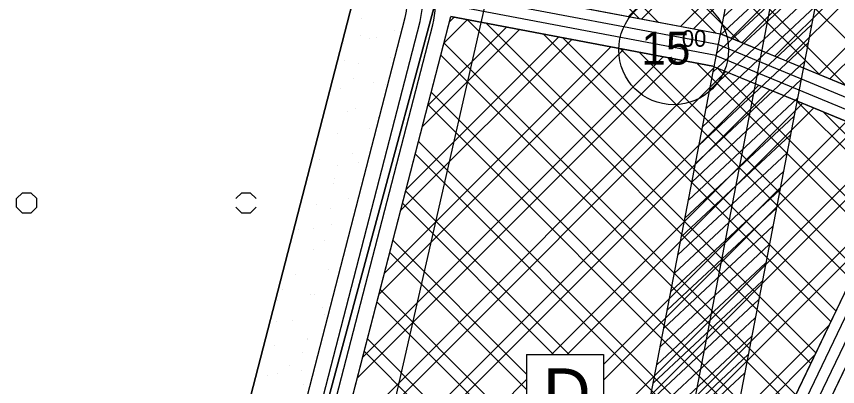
# Model space of a CAD drawing. Extents: x 419109 to 421295, y 4452223 to 4457798.
# Drawn here: x 419705 to 420079.2, y 4455807.8 to 4455976.5 of the extents above; entities that cross this region are included whole.
import ezdxf

# ---------------------------------------------------------------- set-up
doc = ezdxf.new("R2010")
doc.units = 0
for name, color, linetype in [('ADAKENARI', 7, 'Continuous'), ('KALDIRIM_FAT', 7, 'Continuous'), ('KD_DAIRE', 7, 'Continuous'), ('KD_YGEN', 7, 'Continuous'), ('PL_AYA_PARK_DINLENME', 7, 'Continuous'), ('PL_K_DEPOLAMA', 7, 'Continuous'), ('PL_KA_TARIM_ALANI', 7, 'Continuous'), ('PL_TİCARET', 7, 'Continuous'), ('PL_TOPLU_ISYERI', 7, 'Continuous'), ('SEMBOL_FAT', 7, 'Continuous'), ('TA_ENH_154', 7, 'Continuous'), ('TA_ENH_KORUMA', 7, 'Continuous'), ('TA_ENH_TARAMA', 7, 'Continuous'), ('TR_TARIMALANI', 7, 'Continuous'), ('TRFAT_DEPOLAMA', 7, 'Continuous'), ('TRFAT_PARKALANI', 7, 'Continuous'), ('TRFAT_TOPLUİŞYERLERİ', 7, 'Continuous')]:
    doc.layers.add(name, color=color, linetype=linetype)

msp = doc.modelspace()

# ---------------------------------------------------------------- linework, layer by layer
at = {"layer": 'ADAKENARI'}
for p, q in [((420026.68, 4455968.26), (419902.33, 4455991.81)), ((419802.57, 4455768.04), (419857.93, 4455982.18)), ((419826.78, 4455761.78), (419882.14, 4455975.93)), ((419846.14, 4455756.78), (419902.93, 4455976.43)), ((420022.37, 4455953.81), (419902.93, 4455976.43)), ((420026.68, 4455968.26), (420134.21, 4455923.79)), ((420022.37, 4455953.81), (420113.83, 4455915.99)), ((420043.17, 4455733.9), (420134.21, 4455923.79)), ((420029.83, 4455740.78), (420113.83, 4455915.99))]:
    msp.add_line(p, q, dxfattribs=at)
msp.add_arc((419853.67, 4455983.29), 29.41, 345.5054, 77.7533, dxfattribs=at)
at = {"layer": 'KALDIRIM_FAT'}
for p, q in [((420025.24, 4455963.44), (419895.82, 4455987.95)), ((420023.8, 4455958.63), (419896.07, 4455982.82)), ((419833.56, 4455760.03), (419888.92, 4455974.18)), ((419839.36, 4455758.53), (419894.72, 4455972.67)), ((420025.24, 4455963.44), (420120.05, 4455924.24)), ((420023.8, 4455958.63), (420118.13, 4455919.62)), ((420034.28, 4455738.49), (420119.46, 4455916.16)), ((420038.73, 4455736.19), (420123.97, 4455914))]:
    msp.add_line(p, q, dxfattribs=at)
for radius in [42.41, 36.41]:
    msp.add_arc((419853.67, 4455983.29), radius, 345.5054, 77.7533, dxfattribs=at)
at = {"layer": 'KD_DAIRE'}
msp.add_circle((420004.49, 4455961.2), 25, dxfattribs=at)
at = {"layer": 'PL_AYA_PARK_DINLENME'}
for p, q in [((419857.93, 4455982.18), (419802.57, 4455768.04)), ((419826.78, 4455761.78), (419882.14, 4455975.93))]:
    msp.add_line(p, q, dxfattribs=at)
for points in [[(420016.8, 4456927.25), (420013.63, 4456854.22), (420021.56, 4456763.74), (419972.35, 4456528.79), (419896.15, 4456444.66), (419851.71, 4456390.68), (419781.86, 4456219.24), (419743.76, 4456181.14), (419715.18, 4456046.21), (419900.92, 4456001.76), (419824.72, 4455719.19), (419823.13, 4455660.45), (419756.46, 4455592.19), (419783.44, 4455525.52), (419794.56, 4455425.51), (419778.68, 4455323.91)], [(419804.18, 4455325.18), (419819.77, 4455424.95), (419807.91, 4455531.7), (419785.76, 4455586.42), (419835.59, 4455637.43), (419842.19, 4455646.09), (419927.54, 4456021.09), (419744.69, 4456064.85), (419766.68, 4456168.71), (419803.1, 4456205.13), (419873.42, 4456377.73), (419915.08, 4456428.31), (419995.43, 4456517.04), (420046.79, 4456762.24), (420038.67, 4456854.78), (420041.73, 4456924.97)]]:
    msp.add_lwpolyline(points, dxfattribs=at)
msp.add_arc((419853.67, 4455983.29), 29.41, 345.5054, 77.7533, dxfattribs=at)
at = {"layer": 'PL_K_DEPOLAMA'}
msp.add_lwpolyline([(419846.14, 4455756.78), (419902.93, 4455976.43), (420022.37, 4455953.81), (420113.83, 4455915.99), (420029.83, 4455740.78)], dxfattribs=at)
at = {"layer": 'PL_KA_TARIM_ALANI'}
msp.add_lwpolyline([(419792.54, 4455014.98), (419819.96, 4455165.16), (419778.68, 4455323.91), (419794.56, 4455425.51), (419783.44, 4455525.52), (419756.46, 4455592.19), (419823.13, 4455660.45), (419824.72, 4455719.19), (419900.92, 4456001.76), (419869.84, 4456009.19), (419715.18, 4456046.21), (419743.76, 4456181.14), (419781.86, 4456219.24), (419851.71, 4456390.68), (419896.15, 4456444.66), (419972.35, 4456528.79), (420021.56, 4456763.74), (420013.63, 4456854.22), (420016.8, 4456927.25), (420027.91, 4457006.62), (420158.52, 4456994.43), (420142.12, 4457086.4)], dxfattribs=at)
at = {"layer": 'PL_TİCARET'}
msp.add_lwpolyline([(420153.07, 4455976.48), (420152.11, 4455974.16), (420151.45, 4455961.22), (420137.18, 4455930.24), (420134.21, 4455923.79), (420043.17, 4455733.9), (419945.46, 4455556.86), (419940.17, 4455559.7)], dxfattribs=at)
at = {"layer": 'PL_TOPLU_ISYERI'}
msp.add_lwpolyline([(420153.07, 4455976.48), (420152.11, 4455974.16), (420151.45, 4455961.22), (420137.18, 4455930.24), (420134.21, 4455923.79), (420026.68, 4455968.26), (419902.33, 4455991.81)], dxfattribs=at)
at = {"layer": 'SEMBOL_FAT'}
for p, q in [((419937.51, 4455822.43), (419937.51, 4455787.43)), ((419937.51, 4455822.43), (419972.51, 4455822.43)), ((419972.51, 4455822.43), (419972.51, 4455787.43))]:
    msp.add_line(p, q, dxfattribs=at)
at = {"layer": 'TA_ENH_154'}
msp.add_lwpolyline([(419862.83, 4455014.24), (420170.14, 4456613.6), (420230.68, 4456928.68), (420176.89, 4457440.84), (420133.44, 4457787.81)], dxfattribs=at)
at = {"layer": 'TA_ENH_KORUMA'}
msp.add_line((419842.5, 4455014.45), (420150.5, 4456617.38), dxfattribs=at)
msp.add_lwpolyline([(420153.62, 4457787.6), (420196.76, 4457443.12), (420250.88, 4456927.82), (420189.78, 4456609.83), (419883.15, 4455014.02)], dxfattribs=at)
at = {"layer": 'TA_ENH_TARAMA'}
for p, q in [((420027.3, 4455976.24), (420076.95, 4456022.64)), ((420025.7, 4455967.89), (420075.35, 4456014.3)), ((420024.09, 4455959.55), (420073.75, 4456005.95)), ((420022.49, 4455951.21), (420072.14, 4455997.61)), ((420020.89, 4455942.87), (420070.54, 4455989.27)), ((420019.29, 4455934.53), (420068.94, 4455980.93)), ((420017.68, 4455926.18), (420067.33, 4455972.58)), ((420016.08, 4455917.84), (420065.73, 4455964.24)), ((420014.48, 4455909.5), (420064.13, 4455955.9)), ((420012.87, 4455901.16), (420062.53, 4455947.56)), ((420011.27, 4455892.81), (420060.92, 4455939.22)), ((420009.67, 4455884.47), (420059.32, 4455930.87)), ((420008.07, 4455876.13), (420057.72, 4455922.53)), ((420006.46, 4455867.79), (420056.11, 4455914.19)), ((420004.86, 4455859.45), (420054.51, 4455905.85)), ((420003.26, 4455851.1), (420052.91, 4455897.5)), ((420001.65, 4455842.76), (420051.31, 4455889.16)), ((420000.05, 4455834.42), (420049.7, 4455880.82)), ((419998.45, 4455826.08), (420048.1, 4455872.48)), ((419996.84, 4455817.73), (420046.5, 4455864.14)), ((419995.24, 4455809.39), (420044.89, 4455855.79)), ((419993.64, 4455801.05), (420043.29, 4455847.45)), ((419992.04, 4455792.71), (420041.69, 4455839.11)), ((419990.43, 4455784.37), (420040.08, 4455830.77)), ((419988.83, 4455776.02), (420038.48, 4455822.42)), ((419987.23, 4455767.68), (420036.88, 4455814.08))]:
    msp.add_line(p, q, dxfattribs=at)
at = {"layer": 'TR_TARIMALANI'}
for p, q in [((419705, 4455893.42), (419707.71, 4455896.12)), ((419707.75, 4455896.14), (419711.58, 4455896.14)), ((419714.25, 4455893.42), (419711.54, 4455896.12)), ((419805, 4455893.42), (419807.71, 4455896.12)), ((419807.75, 4455896.14), (419811.58, 4455896.14)), ((419814.25, 4455893.42), (419811.54, 4455896.12)), ((419705.04, 4455889.6), (419705.04, 4455893.43)), ((419714.29, 4455889.6), (419714.29, 4455893.43)), ((419707.71, 4455886.88), (419705, 4455889.58)), ((419711.54, 4455886.88), (419714.25, 4455889.58)), ((419807.71, 4455886.88), (419805, 4455889.58)), ((419811.54, 4455886.88), (419814.25, 4455889.58)), ((419707.75, 4455886.89), (419711.58, 4455886.89)), ((419807.75, 4455886.89), (419811.58, 4455886.89))]:
    msp.add_line(p, q, dxfattribs=at)
at = {"layer": 'TRFAT_DEPOLAMA'}
for p, q in [((419899.78, 4455964.26), (419910.51, 4455974.99)), ((419902.25, 4455973.8), (419904.56, 4455976.12)), ((419910.36, 4455975.02), (420067.03, 4455818.35)), ((419889.92, 4455926.12), (419934.29, 4455970.49)), ((419892.38, 4455935.65), (419928.35, 4455971.61)), ((419919.08, 4455973.37), (420069.32, 4455823.13)), ((419882.52, 4455897.51), (419952.13, 4455967.11)), ((419945.25, 4455968.41), (420076.19, 4455837.47)), ((419953.97, 4455966.76), (420078.48, 4455842.25)), ((419872.66, 4455859.36), (419975.91, 4455962.61)), ((419880.06, 4455887.97), (419958.07, 4455965.99)), ((419899.81, 4455964.36), (420060.15, 4455804.01)), ((419870.2, 4455849.83), (419981.85, 4455961.48)), ((419898.35, 4455958.74), (420057.86, 4455799.23)), ((419980.14, 4455961.81), (420085.36, 4455856.59)), ((419988.86, 4455960.15), (420087.65, 4455861.37)), ((419860.34, 4455811.68), (420005.63, 4455956.98)), ((419862.8, 4455821.22), (419999.69, 4455958.1)), ((420015.03, 4455955.2), (420094.52, 4455875.71)), ((419850.47, 4455773.54), (420028.3, 4455951.36)), ((419852.94, 4455783.07), (420023.29, 4455953.43)), ((420024.28, 4455953.02), (420096.81, 4455880.49)), ((419844.49, 4455746.34), (420043.3, 4455945.15)), ((419844.5, 4455739.28), (420048.31, 4455943.08)), ((419894, 4455941.88), (420050.99, 4455784.89)), ((419892.54, 4455936.27), (420048.69, 4455780.11)), ((419948.87, 4455822.43), (420063.31, 4455936.88)), ((420060.45, 4455938.06), (420103.69, 4455894.83)), ((419955.94, 4455822.43), (420068.32, 4455934.81)), ((420072.51, 4455933.08), (420105.98, 4455899.61)), ((419972.51, 4455817.79), (420083.32, 4455928.6)), ((419972.51, 4455810.72), (420088.33, 4455926.54)), ((419841.38, 4455651.3), (420108.34, 4455918.26)), ((419888.19, 4455919.41), (420041.82, 4455765.78)), ((419972.51, 4455789.51), (420103.33, 4455920.33)), ((419886.73, 4455913.79), (420039.53, 4455761)), ((419882.38, 4455896.94), (419956.88, 4455822.43)), ((419834.7, 4455623.42), (420101.45, 4455890.16)), ((419880.92, 4455891.32), (419949.81, 4455822.43)), ((419839.71, 4455621.35), (420094.94, 4455876.58)), ((419876.57, 4455874.46), (419937.51, 4455813.51)), ((419875.11, 4455868.84), (419937.51, 4455806.44)), ((419870.76, 4455851.99), (420012.81, 4455709.93)), ((419869.3, 4455846.37), (420010.3, 4455705.38)), ((419854.71, 4455615.14), (420075.41, 4455835.83)), ((419864.95, 4455829.51), (420002.75, 4455691.71)), ((419859.71, 4455613.07), (420068.89, 4455822.25)), ((419863.49, 4455823.89), (420000.24, 4455687.15)), ((419848.11, 4455721.67), (419937.51, 4455811.08))]:
    msp.add_line(p, q, dxfattribs=at)
at = {"layer": 'TRFAT_PARKALANI'}
for p, q in [((419862.37, 4455975.69), (419862.37, 4455975.69)), ((419877.51, 4455970.04), (419877.51, 4455970.04)), ((419861.87, 4455967.72), (419861.87, 4455967.72)), ((419869.03, 4455966.71), (419869.03, 4455966.71)), ((419854.26, 4455964.1), (419854.26, 4455964.1)), ((419865.82, 4455966.18), (419865.82, 4455966.18)), ((419854.33, 4455956.54), (419854.33, 4455956.54)), ((419860.92, 4455955.12), (419860.92, 4455955.12)), ((419875.69, 4455957.73), (419875.69, 4455957.73)), ((419858.4, 4455948.02), (419858.4, 4455948.02)), ((419867.58, 4455946.14), (419867.58, 4455946.14)), ((419873.17, 4455945.42), (419873.17, 4455945.42)), ((419852.8, 4455943.54), (419852.8, 4455943.54)), ((419855.79, 4455933.25), (419855.79, 4455933.25)), ((419859.46, 4455934.56), (419859.46, 4455934.56)), ((419869.78, 4455930.34), (419869.78, 4455930.34)), ((419866.13, 4455925.58), (419866.13, 4455925.58)), ((419851.35, 4455922.97), (419851.35, 4455922.97)), ((419858.01, 4455913.99), (419858.01, 4455913.99)), ((419843.24, 4455911.39), (419843.24, 4455911.39)), ((419851.45, 4455908.63), (419851.45, 4455908.63)), ((419860.89, 4455909.82), (419860.89, 4455909.82)), ((419849.4, 4455900.18), (419849.4, 4455900.18)), ((419849.9, 4455902.41), (419849.9, 4455902.41)), ((419856.56, 4455893.43), (419856.56, 4455893.43)), ((419841.79, 4455890.83), (419841.79, 4455890.83)), ((419847.98, 4455888.93), (419847.98, 4455888.93)), ((419848.45, 4455881.85), (419848.45, 4455881.85)), ((419833.68, 4455879.24), (419833.68, 4455879.24)), ((419840.51, 4455879.67), (419840.51, 4455879.67)), ((419845.37, 4455874.16), (419845.37, 4455874.16)), ((419855.11, 4455872.87), (419855.11, 4455872.87)), ((419829.02, 4455870.02), (419829.02, 4455870.02)), ((419829.73, 4455871.84), (419829.73, 4455871.84)), ((419840.34, 4455870.26), (419840.34, 4455870.26)), ((419832.23, 4455858.68), (419832.23, 4455858.68)), ((419847, 4455861.28), (419847, 4455861.28)), ((419826.26, 4455852.15), (419826.26, 4455852.15)), ((419824.12, 4455847.09), (419824.12, 4455847.09)), ((419838.89, 4455849.7), (419838.89, 4455849.7)), ((419841.03, 4455849.54), (419841.03, 4455849.54)), ((419844.47, 4455843.83), (419844.47, 4455843.83)), ((419845.55, 4455840.72), (419845.55, 4455840.72)), ((419823.65, 4455837.37), (419823.65, 4455837.37)), ((419830.78, 4455838.11), (419830.78, 4455838.11)), ((419837.44, 4455829.13), (419837.44, 4455829.13)), ((419837.56, 4455829.85), (419837.56, 4455829.85)), ((419822.67, 4455826.53), (419822.67, 4455826.53)), ((419835.58, 4455823.31), (419835.58, 4455823.31)), ((419829.33, 4455817.55), (419829.33, 4455817.55)), ((419824.09, 4455813.67), (419824.09, 4455813.67)), ((419834.95, 4455815.07), (419834.95, 4455815.07)), ((419819.31, 4455812.75), (419819.31, 4455812.75)), ((419835.99, 4455808.57), (419835.99, 4455808.57))]:
    msp.add_line(p, q, dxfattribs=at)
at = {"layer": 'TRFAT_TOPLUİŞYERLERİ'}
for p, q in [((420197.95, 4456155.09), (420013.6, 4455970.74)), ((420188.58, 4456152.79), (420007.65, 4455971.86)), ((420215.72, 4456151.64), (420030.68, 4455966.6)), ((420160.49, 4456145.91), (419989.82, 4455975.24)), ((420219.25, 4456148.11), (420035.68, 4455964.54)), ((419821.29, 4456143.02), (419988.89, 4455975.42)), ((420151.13, 4456143.62), (419983.87, 4455976.37)), ((419922.8, 4456126.36), (420119.13, 4455930.03)), ((420210.62, 4456118.26), (420050.69, 4455958.33)), ((420205.83, 4456106.4), (420055.69, 4455956.26)), ((420192.46, 4456071.82), (420070.7, 4455950.06)), ((420187.48, 4456059.77), (420075.7, 4455947.99)), ((419969.04, 4456058.91), (420082.96, 4455944.99)), ((419969.04, 4456051.84), (420070.9, 4455949.97)), ((419939.54, 4456031.84), (419997.61, 4455973.76)), ((419960.75, 4456031.84), (420023.78, 4455968.81)), ((419967.83, 4456031.84), (420034.73, 4455964.93))]:
    msp.add_line(p, q, dxfattribs=at)

# ---------------------------------------------------------------- texts
at = {"layer": 'KD_YGEN'}
for s, height, p in [('00', 7.5, (420008.24, 4455962.65)), ('15', 15, (419989.83, 4455954.5))]:
    msp.add_text(s, height=height, dxfattribs=at).set_placement(p)
at = {"layer": 'SEMBOL_FAT'}
msp.add_text('D', height=22.5, dxfattribs=at).set_placement((419944.96, 4455793.59))

doc.saveas('drawing.dxf')
